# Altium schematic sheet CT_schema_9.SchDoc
size 387 x 278 mm
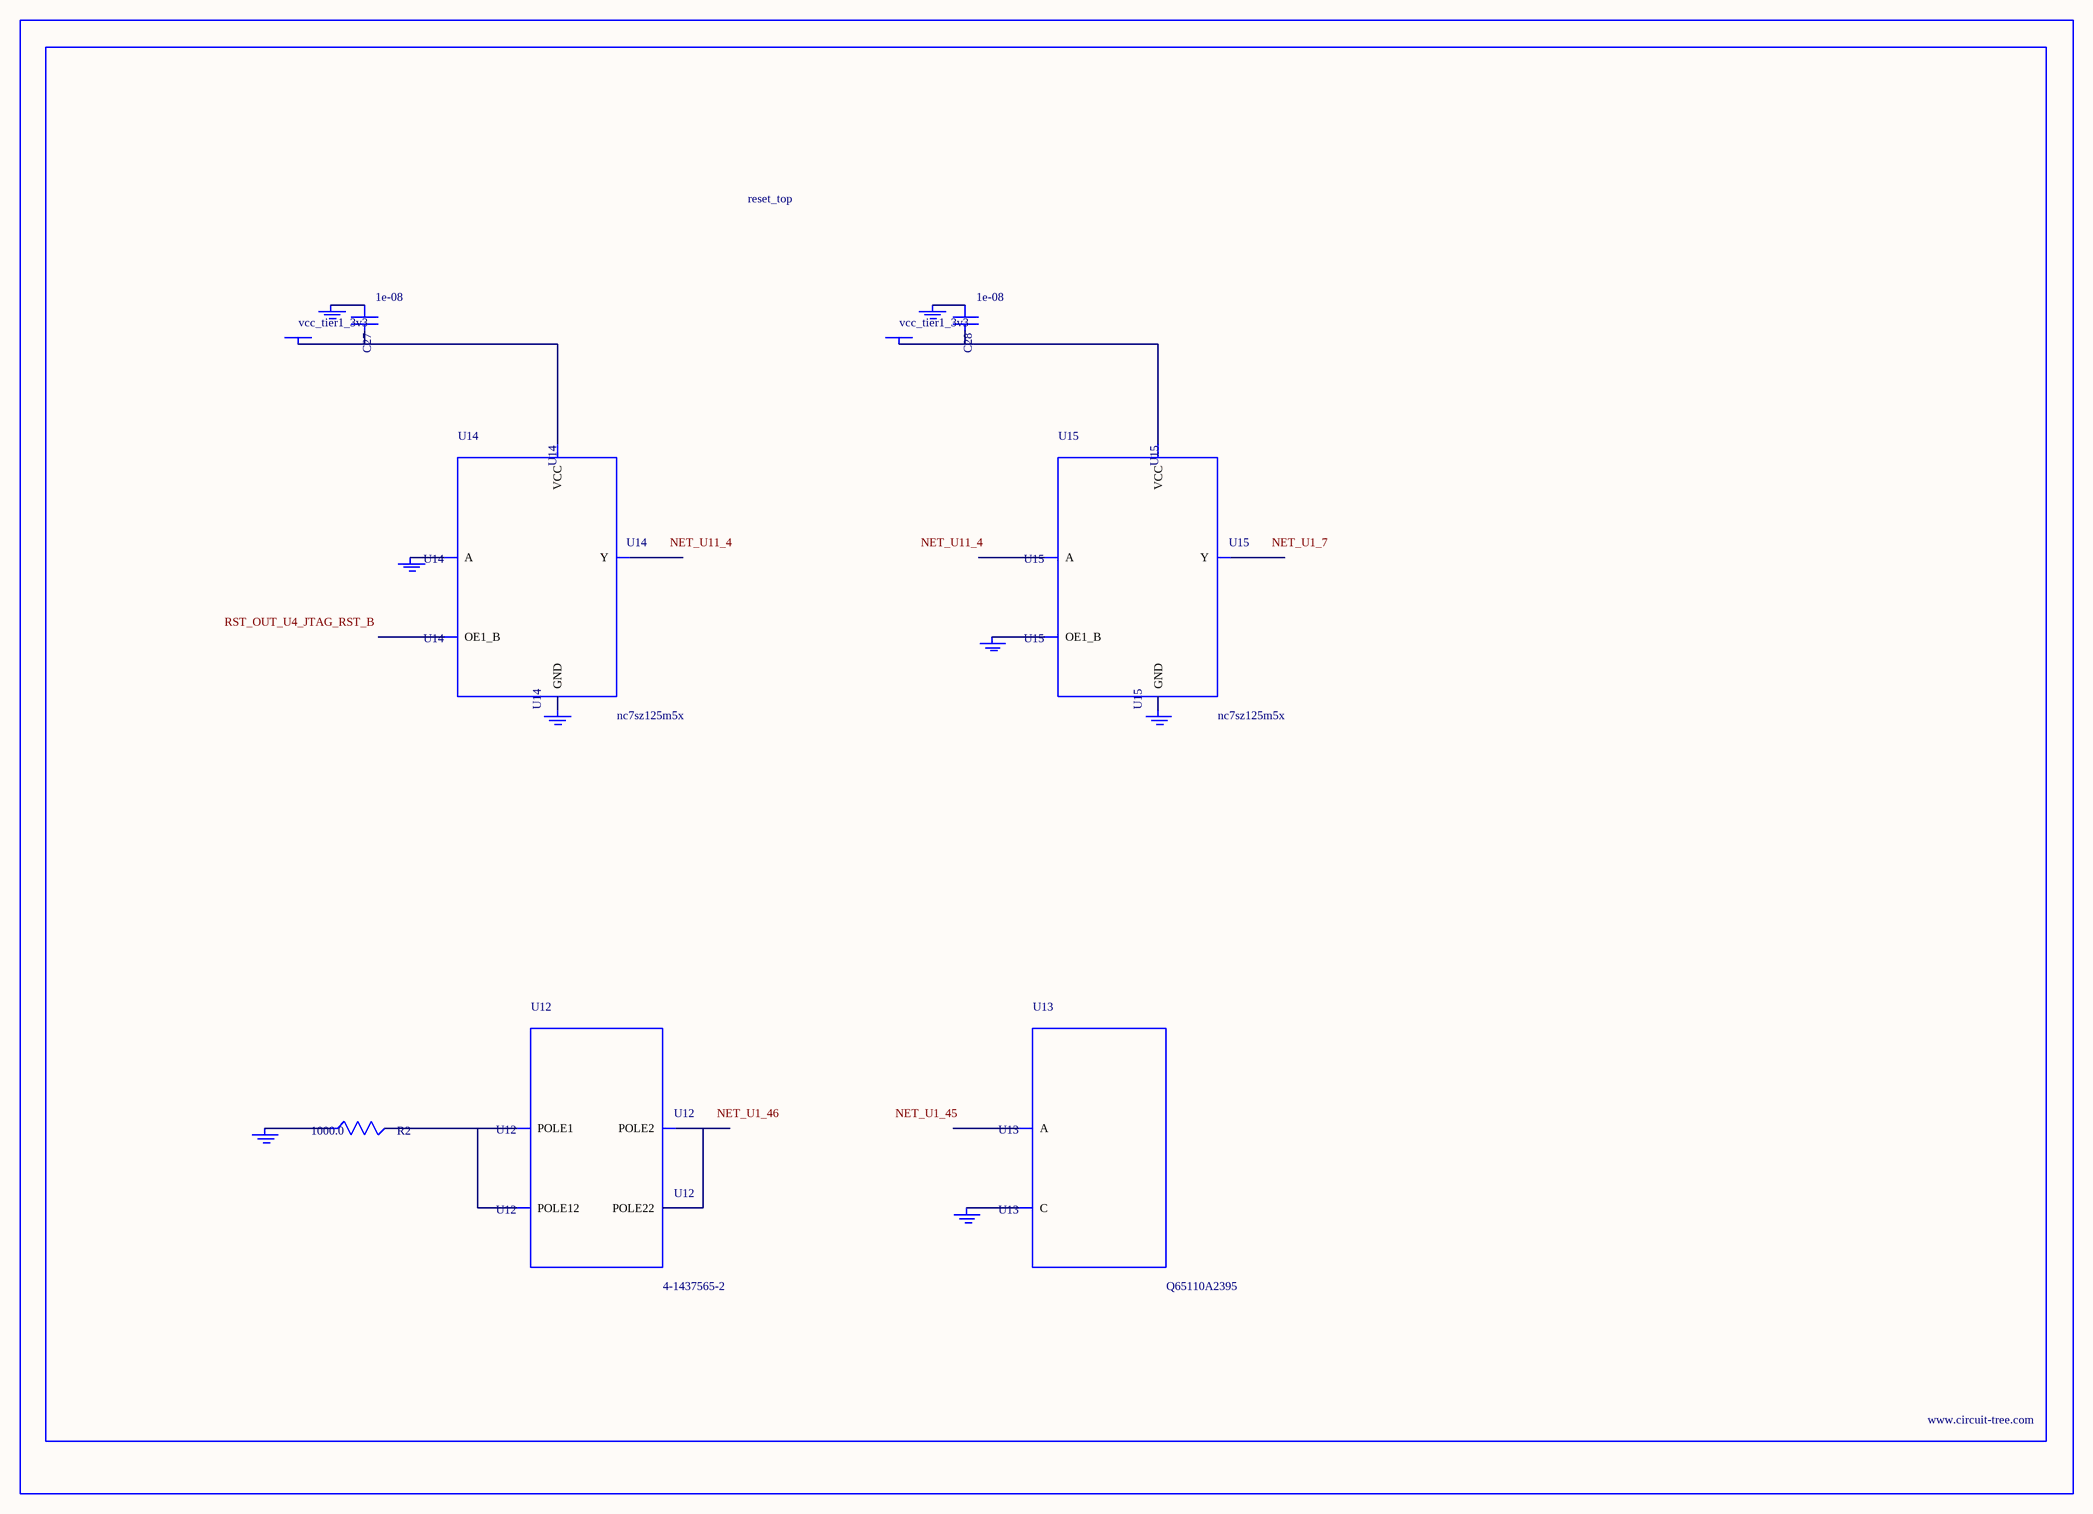
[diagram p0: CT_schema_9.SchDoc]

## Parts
BORDER8  (no value)
C27  1e-08  [C0402]
C28  1e-08  [C0402]
GND_INSTANCE_8_0  (no value)
GND_INSTANCE_8_1  (no value)
GND_INSTANCE_8_2  (no value)
GND_INSTANCE_8_3  (no value)
GND_INSTANCE_8_4  (no value)
GND_INSTANCE_8_5  (no value)
GND_INSTANCE_8_6  (no value)
GND_INSTANCE_8_7  (no value)
POWER_INSTANCE_8_0  vcc_tier1_3v3
POWER_INSTANCE_8_1  vcc_tier1_3v3
R2  1000.0  [R0603]
U12  4-1437565-2  [SW_4-1437565-2]
U13  Q65110A2395  [LGM67K-G1J2-24-Z]
U14  nc7sz125m5x  [NC7SZ125M5X]
U15  nc7sz125m5x  [NC7SZ125M5X]

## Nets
NetC27_1: C27.1 GND_INSTANCE_8_2.0(GND)
NetC27_2: C27.2 POWER_INSTANCE_8_0.0(PWR) U14.5(VCC)
NetC28_1: C28.1 GND_INSTANCE_8_5.0(GND)
NetC28_2: C28.2 POWER_INSTANCE_8_1.0(PWR) U15.5(VCC)
NetGND_INSTANCE_8_0_0: GND_INSTANCE_8_0.0(GND) R2.1
NetGND_INSTANCE_8_1_0: GND_INSTANCE_8_1.0(GND) U13.C
NetGND_INSTANCE_8_3_0: GND_INSTANCE_8_3.0(GND) U14.2(A)
NetGND_INSTANCE_8_4_0: GND_INSTANCE_8_4.0(GND) U14.3(GND)
NetGND_INSTANCE_8_6_0: GND_INSTANCE_8_6.0(GND) U15.1(OE1_B)
NetGND_INSTANCE_8_7_0: GND_INSTANCE_8_7.0(GND) U15.3(GND)
NetR2_2: R2.2 U12.1(POLE1) U12.2(POLE12)
NetU12_3: U12.3(POLE2) U12.4(POLE22)

Not connected (* = marked no-connect by the designer): U13 A; U14 1(OE1_B) 4(Y); U15 2(A) 4(Y)

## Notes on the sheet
- Labels drawn without touching a wire or pin: NET_U1_7, NET_U1_45, NET_U1_46, NET_U11_4, RST_OUT_U4_JTAG_RST_B

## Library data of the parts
BORDER8 = BORDER_PAGE8
C27 C28 = C0402C103K3RAC
GND_INSTANCE_8_0-GND_INSTANCE_8_7 = GND
POWER_INSTANCE_8_0 POWER_INSTANCE_8_1 = PWR
R2 = RC0603JR-071KL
